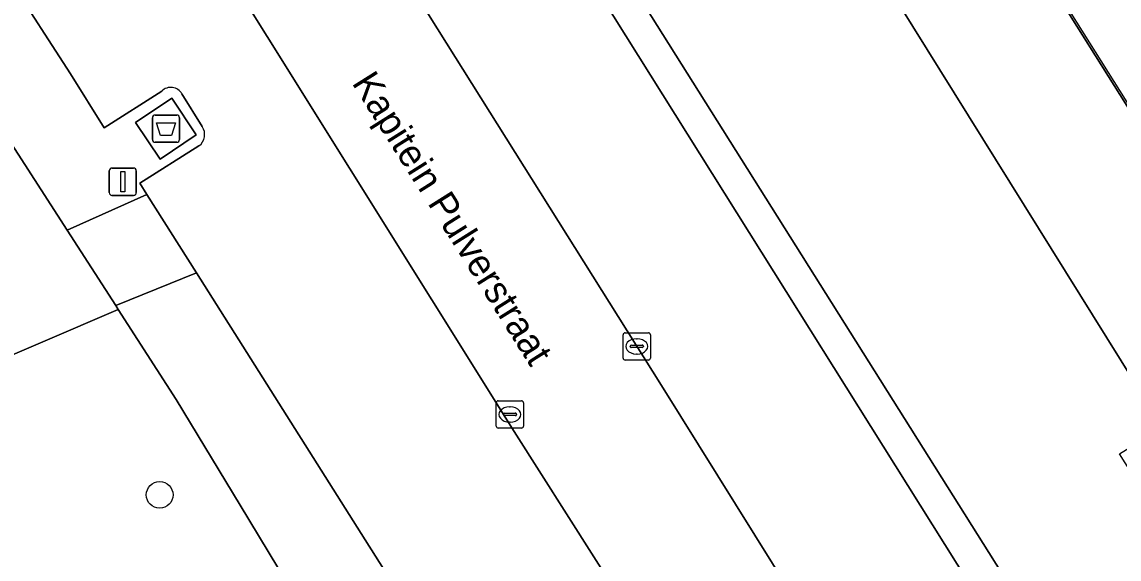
# Model space of a CAD drawing. Extents: x 160077 to 160948, y 386481 to 387498.
# Drawn here: x 160384.29 to 160424.49, y 386932.94 to 386952.63 of the extents above; entities that cross this region are included whole.
import ezdxf

# ---------------------------------------------------------------- set-up
doc = ezdxf.new("R2010")
doc.units = 0
for name, color, linetype in [('IMGEO_Afval_apart_plaats', 7, 'Continuous'), ('IMGEO_Boom', 7, 'Continuous'), ('IMGEO_Erf', 7, 'Continuous'), ('IMGEO_Groenvoorziening', 7, 'Continuous'), ('IMGEO_Hek', 7, 'Continuous'), ('IMGEO_Kolk', 7, 'Continuous'), ('IMGEO_Lichtmast', 7, 'Continuous'), ('IMGEO_Openbare_ruimte_label', 7, 'Continuous'), ('IMGEO_Parkeervlak_open', 7, 'Continuous'), ('IMGEO_Rijbaan_lokaal_open', 7, 'Continuous'), ('IMGEO_Voetpad_gesloten', 7, 'Continuous'), ('IMGEO_Voetpad_open', 7, 'Continuous')]:
    doc.layers.add(name, color=color, linetype=linetype)

msp = doc.modelspace()

# ---------------------------------------------------------------- linework, layer by layer
at = {"layer": 'IMGEO_Afval_apart_plaats'}
for p, q in [((160389.075, 386948.32), (160389.075, 386949.12)), ((160389.075, 386949.12), (160389.075, 386948.32)), ((160389.175, 386949.22), (160389.965, 386949.22)), ((160389.965, 386949.22), (160389.175, 386949.22)), ((160390.065, 386949.12), (160390.065, 386948.32)), ((160390.065, 386948.32), (160390.065, 386949.12)), ((160389.965, 386948.22), (160389.175, 386948.22)), ((160389.175, 386948.22), (160389.965, 386948.22))]:
    msp.add_line(p, q, dxfattribs=at)
msp.add_lwpolyline([(160389.218, 386948.934), (160389.922, 386948.934), (160389.773, 386948.464), (160389.367, 386948.464), (160389.218, 386948.934)], dxfattribs=at)
for centre, start, end in [((160389.175, 386949.12), 90, 180), ((160389.175, 386949.12), 90, 180), ((160389.965, 386949.12), 0, 90), ((160389.965, 386949.12), 360, 90), ((160389.175, 386948.32), 180, 270), ((160389.175, 386948.32), 180, 270), ((160389.965, 386948.32), 270, 0), ((160389.965, 386948.32), 270, 0)]:
    msp.add_arc(centre, 0.1, start, end, dxfattribs=at)
at = {"layer": 'IMGEO_Boom'}
msp.add_circle((160389.339, 386935.296), 0.489, dxfattribs=at)
at = {"layer": 'IMGEO_Erf'}
msp.add_lwpolyline([(160473.137, 386972.655), (160453.975, 387003.205), (160430.516, 386988.451), (160431.817, 386986.382), (160437.856, 386976.782), (160436.662, 386976.031), (160430.668, 386985.657), (160429.375, 386987.733), (160408.886, 386974.847), (160415.725, 386963.966), (160416.309, 386963.036), (160430.464, 386940.512), (160434.156, 386934.637), (160441.379, 386922.838), (160445.701, 386916.313), (160449.013, 386911.065), (160450.499, 386908.528)], dxfattribs=at)
at = {"layer": 'IMGEO_Groenvoorziening'}
for points in [[(160416.309, 386963.036), (160412.008, 386960.369), (160413.372, 386958.18), (160426.082, 386937.782), (160429.547, 386939.941), (160430.464, 386940.512)], [(160413.372, 386958.18), (160409.654, 386955.863), (160406.679, 386953.933), (160423.283, 386927.515), (160428.214, 386930.912), (160426.619, 386933.446), (160424.504, 386936.799), (160426.082, 386937.782)]]:
    msp.add_lwpolyline(points, close=True, dxfattribs=at)
for points in [[(160387.823, 386942.091), (160382.202, 386939.689), (160383.11, 386937.529), (160379.951, 386936.149), (160400.589, 386887.504), (160401.965, 386888.113), (160404.29, 386882.638), (160402.891, 386882.025), (160403.874, 386879.763), (160405.479, 386880.09)], [(160409.893, 386881.917), (160411.377, 386882.716), (160417.798, 386886.204), (160421.525, 386888.269), (160416.406, 386896.516), (160412.535, 386902.752), (160408.864, 386908.506), (160403.038, 386917.636), (160399.533, 386923.281), (160396.796, 386927.687), (160394.729, 386930.878), (160392.284, 386934.918), (160389.939, 386938.794), (160387.823, 386942.091)]]:
    msp.add_lwpolyline(points, dxfattribs=at)
at = {"layer": 'IMGEO_Hek'}
msp.add_lwpolyline([(160447.699, 386913.245), (160415.689, 386964.174)], dxfattribs=at)
at = {"layer": 'IMGEO_Kolk'}
for p, q in [((160406.318, 386940.313), (160406.318, 386941.165)), ((160406.393, 386941.239), (160407.245, 386941.239)), ((160406.806, 386941.019), (160406.831, 386941.019)), ((160407.319, 386941.165), (160407.319, 386940.313)), ((160406.577, 386940.733), (160406.577, 386940.745)), ((160407.015, 386940.696), (160406.617, 386940.696)), ((160406.62, 386940.782), (160407.018, 386940.782)), ((160407.061, 386940.745), (160407.061, 386940.733)), ((160407.245, 386940.239), (160406.393, 386940.239)), ((160406.829, 386940.459), (160406.804, 386940.459)), ((160401.669, 386937.818), (160401.669, 386938.67)), ((160401.744, 386938.744), (160402.596, 386938.744)), ((160402.157, 386938.524), (160402.182, 386938.524)), ((160402.67, 386938.67), (160402.67, 386937.818)), ((160401.928, 386938.238), (160401.928, 386938.25)), ((160402.366, 386938.201), (160401.968, 386938.201)), ((160401.971, 386938.287), (160402.369, 386938.287)), ((160402.412, 386938.25), (160402.412, 386938.238)), ((160402.596, 386937.744), (160401.744, 386937.744)), ((160402.18, 386937.964), (160402.155, 386937.964))]:
    msp.add_line(p, q, dxfattribs=at)
for points in [[(160406.318, 386940.313), (160406.318, 386941.165)], [(160406.393, 386941.239), (160407.245, 386941.239)], [(160407.319, 386941.165), (160407.319, 386940.313)], [(160407.245, 386940.239), (160406.393, 386940.239)], [(160401.669, 386937.818), (160401.669, 386938.67)], [(160401.744, 386938.744), (160402.596, 386938.744)], [(160402.67, 386938.67), (160402.67, 386937.818)], [(160402.596, 386937.744), (160401.744, 386937.744)]]:
    msp.add_lwpolyline(points, dxfattribs=at)
for centre, radius, start, end in [((160406.395, 386941.163), 0.0765, 91.552, 178.448), ((160406.395, 386941.163), 0.0765, 91.552, 178.448), ((160407.243, 386941.163), 0.0765, 1.552, 88.448), ((160407.243, 386941.163), 0.0765, 1.552, 88.448), ((160406.617, 386940.742), 0.0403, 85.8775, 175.7526), ((160406.614, 386940.732), 0.0366, 178.938, 274.7102), ((160407.018, 386940.739), 0.043, 264.8664, 352.4533), ((160407.022, 386940.744), 0.0386, 1.7309, 96.639), ((160406.395, 386940.315), 0.0765, 181.552, 268.448), ((160406.395, 386940.315), 0.0765, 181.552, 268.448), ((160407.243, 386940.315), 0.0765, 271.552, 358.448), ((160407.243, 386940.315), 0.0765, 271.552, 358.448), ((160401.746, 386938.668), 0.0765, 91.552, 178.448), ((160401.746, 386938.668), 0.0765, 91.552, 178.448), ((160402.594, 386938.668), 0.0765, 1.552, 88.448), ((160402.594, 386938.668), 0.0765, 1.552, 88.448), ((160401.968, 386938.247), 0.0403, 85.8775, 175.7526), ((160401.965, 386938.237), 0.0366, 178.938, 274.7102), ((160402.369, 386938.244), 0.043, 264.8664, 352.4533), ((160402.373, 386938.249), 0.0386, 1.7309, 96.639), ((160401.746, 386937.82), 0.0765, 181.552, 268.448), ((160401.746, 386937.82), 0.0765, 181.552, 268.448), ((160402.594, 386937.82), 0.0765, 271.552, 358.448), ((160402.594, 386937.82), 0.0765, 271.552, 358.448)]:
    msp.add_arc(centre, radius, start, end, dxfattribs=at)
for centre, major_axis, ratio, start_param, end_param in [((160406.805, 386940.739), (-0.387, 0.002), 0.722429, 4.712389, 7.853982), ((160406.83, 386940.739), (-0.39, 0.002), 0.717154, 1.570796, 4.712389), ((160402.156, 386938.244), (-0.387, 0.002), 0.722429, 4.712389, 7.853982), ((160402.181, 386938.244), (-0.39, 0.002), 0.717154, 1.570796, 4.712389)]:
    msp.add_ellipse(centre, major_axis=major_axis, ratio=ratio, start_param=start_param, end_param=end_param, dxfattribs=at)
at = {"layer": 'IMGEO_Lichtmast'}
for p, q in [((160387.493, 386946.374), (160387.493, 386947.174)), ((160387.493, 386947.174), (160387.493, 386946.374)), ((160387.593, 386947.274), (160388.383, 386947.274)), ((160388.383, 386947.274), (160387.593, 386947.274)), ((160388.483, 386947.174), (160388.483, 386946.374)), ((160388.483, 386946.374), (160388.483, 386947.174)), ((160388.383, 386946.274), (160387.593, 386946.274)), ((160387.593, 386946.274), (160388.383, 386946.274))]:
    msp.add_line(p, q, dxfattribs=at)
msp.add_lwpolyline([(160387.913, 386947.149), (160388.063, 386947.149), (160388.063, 386946.399), (160387.913, 386946.399), (160387.913, 386947.149)], dxfattribs=at)
for centre, start, end in [((160387.593, 386947.174), 90, 180), ((160387.593, 386947.174), 90, 180), ((160388.383, 386947.174), 0, 90), ((160388.383, 386947.174), 360, 90), ((160387.593, 386946.374), 180, 270), ((160387.593, 386946.374), 180, 270), ((160388.383, 386946.374), 270, 0), ((160388.383, 386946.374), 270, 0)]:
    msp.add_arc(centre, 0.1, start, end, dxfattribs=at)
at = {"layer": 'IMGEO_Parkeervlak_open'}
for points in [[(160385.916, 386965.458), (160379.288, 386961.228), (160386.077, 386950.727), (160387.305, 386948.746), (160389.414, 386950.096)], [(160394.157, 386960.926), (160407.72, 386939.3), (160421.339, 386917.461), (160423.535, 386918.746), (160426.233, 386920.508), (160400.541, 386961.501)], [(160390.779, 386948.087), (160388.615, 386946.721), (160388.875, 386946.31), (160390.688, 386943.438), (160411.153, 386911.02), (160416.321, 386914.248), (160416.924, 386914.647), (160402.32, 386937.614), (160390.263, 386956.936), (160388.955, 386959.055), (160387.906, 386960.997)], [(160390.152, 386949.993), (160390.898, 386948.796)]]:
    msp.add_lwpolyline(points, dxfattribs=at)
for centre, radius, start, end in [((160389.745, 386949.77), 0.464, 28.6727, 135.4368), ((160390.465, 386948.504), 0.522, 306.9643, 33.98)]:
    msp.add_arc(centre, radius, start, end, dxfattribs=at)
at = {"layer": 'IMGEO_Rijbaan_lokaal_open'}
msp.add_lwpolyline([(160387.906, 386960.997), (160388.955, 386959.055), (160390.263, 386956.936), (160402.32, 386937.614), (160416.924, 386914.647), (160416.321, 386914.248), (160419.644, 386908.926), (160414.476, 386905.699), (160418.626, 386899.176), (160445.701, 386916.313), (160441.379, 386922.838), (160437.094, 386920.111), (160426.867, 386913.603), (160423.535, 386918.746), (160421.339, 386917.461), (160407.72, 386939.3), (160394.157, 386960.926)], dxfattribs=at)
at = {"layer": 'IMGEO_Voetpad_gesloten'}
msp.add_lwpolyline([(160389.779, 386949.835), (160388.458, 386948.949), (160389.36, 386947.605), (160390.681, 386948.491)], close=True, dxfattribs=at)
at = {"layer": 'IMGEO_Voetpad_open'}
for points in [[(160384.296, 386968.171), (160375.091, 386962.445), (160380.863, 386953.4), (160380.291, 386953.014), (160381.9, 386950.487), (160382.328, 386950.748), (160383.799, 386948.34), (160385.948, 386945.002), (160388.875, 386946.31), (160388.615, 386946.721), (160390.779, 386948.087)], [(160389.414, 386950.096), (160387.305, 386948.746), (160386.077, 386950.727), (160379.288, 386961.228), (160385.916, 386965.458)], [(160400.541, 386961.501), (160426.233, 386920.508), (160427.264, 386921.181), (160423.283, 386927.515), (160406.679, 386953.933), (160401.452, 386962.248)], [(160390.898, 386948.796), (160390.152, 386949.993)], [(160382.202, 386939.689), (160387.823, 386942.091), (160387.728, 386942.238), (160385.948, 386945.002), (160383.799, 386948.34)]]:
    msp.add_lwpolyline(points, dxfattribs=at)
for points in [[(160389.779, 386949.835), (160390.681, 386948.491), (160389.36, 386947.605), (160388.458, 386948.949)], [(160388.875, 386946.31), (160385.948, 386945.002), (160387.728, 386942.238), (160390.688, 386943.438)], [(160414.476, 386905.699), (160411.153, 386911.02), (160390.688, 386943.438), (160387.728, 386942.238), (160387.823, 386942.091), (160389.939, 386938.794), (160392.284, 386934.918), (160394.729, 386930.878), (160396.796, 386927.687), (160399.533, 386923.281), (160403.038, 386917.636), (160408.864, 386908.506), (160412.535, 386902.752), (160416.406, 386896.516), (160421.525, 386888.269), (160424.466, 386889.949), (160418.626, 386899.176)]]:
    msp.add_lwpolyline(points, close=True, dxfattribs=at)
for centre, radius, start, end in [((160389.745, 386949.77), 0.464, 28.6727, 135.4368), ((160390.465, 386948.504), 0.522, 306.9643, 33.98)]:
    msp.add_arc(centre, radius, start, end, dxfattribs=at)

# ---------------------------------------------------------------- texts
at = {"layer": 'IMGEO_Openbare_ruimte_label'}
msp.add_text('Kapitein Pulverstraat', height=1, rotation=302.2119, dxfattribs=at).set_placement((160396.36, 386950.396))

doc.saveas('drawing.dxf')
